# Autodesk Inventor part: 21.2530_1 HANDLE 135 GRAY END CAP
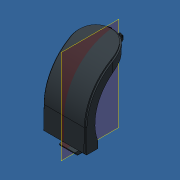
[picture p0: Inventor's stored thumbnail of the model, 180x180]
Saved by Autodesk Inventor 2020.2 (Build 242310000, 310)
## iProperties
Created: 2016-08
Part Number: 21.2530_1 HANDLE 135 GRAY END CAP
Material: PA 6.6
Document SubType Name: Modeling
Designer: MuellerJ
Mass: 1.18836 g
Surface Area: 16.7325 cm^2
Volume: 1.1211 cm^3
Density: 1.06 g/cm^3
Appearance: RAL 7012 Basaltgrau
Description: Abdeckkappe - Handgriff Einzelteil
Beschreibung: Abdeckkappe - Handgriff Einzelteil
Bezeichnung: Abdeckkappe - Handgriff Einzelteil
Artikelnr: 212531/0
Klassifizierung: Griffe,Schlösser,Anschläge
Lieferantennr: 72401
Zeichnungsnr: 21-2531-0FZ.001
MiniTec_ID: 212531/0
Teileart: ART
Lieferant: MiniTec
Author: MuellerJ
Title: Abdeckkappe - Handgriff Einzelteil
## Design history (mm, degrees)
feature "8931"
feature "Körper verschieben1"
node "Volumenkörper1"
other parameters: "d0" = -8, "d1" = 0, "d2" = 0
